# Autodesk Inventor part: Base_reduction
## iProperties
Shininess: 64.0
Length Units: 11269
Angle Units: 11279
Time Units: 11290
Mass Units: 11283
Length Display Precision: 3
Angle Display Precision: 2
Compacted: True
Part Number: Base_reduction
Document SubType Name: Modeling
Created: 2008-02
Material: Acier doux
Designer: Pascal
Density: 0.0
Volumn: 0.0
Area: 0.0
PropertySet Name: Model Information
Control State: 0
Master: False
Checked Out: False
DESIGNATION: Réduction rond/rectangle
Author: Pascal
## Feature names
1. Lissage1
2. Coque1
